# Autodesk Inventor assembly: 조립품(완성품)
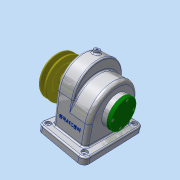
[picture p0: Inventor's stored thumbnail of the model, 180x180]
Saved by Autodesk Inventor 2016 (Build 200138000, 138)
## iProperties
Created: 2017-11
Part Number: 조립품(완성품)
Material: 일반
Document SubType Name: Assembly
Designer: 605-17
Author: 605-17
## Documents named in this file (12)
- C:\Users\605-17\Desktop\471107V1029\조립품(완성품).iam
- C:\Users\605-17\Desktop\471107V1029\부품(완성품).ipt
- C:\Users\605-17\Desktop\471107V1029\앞커버.ipt
- C:\Users\605-17\Desktop\471107V1029\오일 실 15 30 7.ipt
- C:\Users\605-17\Desktop\471107V1029\볼트 M3 x 8.ipt
- C:\Users\605-17\Desktop\471107V1029\축.ipt
- C:\Users\605-17\Desktop\471107V1029\베어링 6002.ipt
- C:\Users\605-17\Desktop\471107V1029\키 - 6 x 6 x 22.ipt
- C:\Users\605-17\Desktop\471107V1029\뒤커버.ipt
- C:\Users\605-17\Desktop\471107V1029\V-벨트풀리.ipt
- C:\Users\605-17\Desktop\471107V1029\멈춤나사 - M4 x 10.ipt
- 멈춤나사 - M4 x 10.ipt
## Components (1 placed, 1 different names)
1. V-벨트풀리:1
